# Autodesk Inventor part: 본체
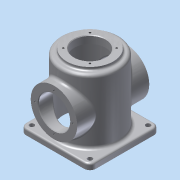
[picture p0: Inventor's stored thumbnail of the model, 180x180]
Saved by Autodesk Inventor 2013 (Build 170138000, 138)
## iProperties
Created: 2015-10
Part Number: 본체
Material: 알루미늄 6061
Document SubType Name: Modeling
Designer: Administrator
Density: 2.71 g/cm^3
Mass: 985.996 g
Surface Area: 1037.34 cm^2
Volume: 363.836 cm^3
Author: Administrator
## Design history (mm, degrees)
sketch "스케치1"
  geometry: L1 (-50, 60)-(50, 60); L2 (60, 50)-(60, -50); L3 (50, -60)-(-50, -60); L4 (-60, -50)-(-60, 50); A1 r 10 centre (-50, 50) between (-50, 60) and (-60, 50); A2 r 10 centre (-50, -50) between (-60, -50) and (-50, -60); A3 r 10 centre (50, -50) between (50, -60) and (60, -50); A4 r 10 centre (50, 50) between (60, 50) and (50, 60); 5 further points
  constraints: 8 end point, 8 point on circle, 8 tangent, 4 centre point, 4 point on line, 3 equal radius, 2 midpoint, 2 parallel, 2 perpendicular, 1 horizontal, 1 horizontal alignment, 1 vertical alignment
  dimensions: "d0" = 120 distance of point (-60, 60) point (60, 60); "d2" = 10 radius of A1
extrude "돌출1" new body sketch "스케치1" distance "d3" = 10; taper "d4" = 0 deg
sketch "스케치2"
  geometry: C1 r 50 at (0, 0); 1 further point
  constraints: 1 centre point, 1 coincident
  dimensions: "d5" = 100 diameter of C1
extrude "돌출2" join sketch "스케치2" distance "d7" = 110; taper "d8" = 0 deg
sketch "스케치3"
  geometry: C1 r 40 at (0, 0); 1 further point
  constraints: 1 centre point, 1 coincident
  dimensions: "d9" = 80 diameter of C1
extrude "돌출3" join sketch "스케치3" distance "d11" = 5; taper "d12" = 0 deg
sketch "스케치4"
  geometry: C1 r 40 at (0, 60); 1 further point
  constraints: 1 centre point, 1 vertical alignment
  dimensions: "d13" = 80 diameter of C1; "d15" = 60 distance of point (0, 0) C1.centre
extrude "돌출4" join sketch "스케치4" stored distance "d16" = 124; taper "d17" = 0 deg
node "작업 평면1"
sketch "스케치5"
  geometry: L1 (-39.988, 60.696)-(-39.988, 79.304); L2 (-39.988, 79.304)-(39.988, 79.304); L3 (39.988, 79.304)-(39.988, 60.696); L4 (39.988, 60.696)-(-39.988, 60.696); 4 further points
  constraints: 2 midpoint, 2 vertical alignment, 1 horizontal alignment, 2 other
  dimensions: "d19" = 70 distance of point (0, 0) point (0, 70)
feature "엠보싱1" sketch "스케치5" dims "d0" = 120, "d2" = 10, "d9" = 80, "d20" = 0.5, "d21" = 0
hole "구멍1" diameter "d24" = 54; stored, may be unused: countersink angle "d28" = 90 deg, drill point angle "d30" = 0 deg; dims "d22" = 10, "d23" = 10, "d25" = 6, "d26" = 90, "d27" = 112, "d29" = 125
hole "구멍2" diameter "d33" = 54; stored, may be unused: countersink angle "d37" = 90 deg, drill point angle "d39" = 0 deg; dims "d31" = 10, "d32" = 10, "d34" = 6, "d35" = 90, "d36" = 112, "d38" = 125
sketch "스케치6"
  geometry: A1 r 32.5 centre (0, 0) between (0, 32.5) and (0, -32.5); 3 further points
  constraints: 4 point on circle, 3 vertical alignment, 2 horizontal alignment, 1 centre point
  dimensions: "d40" = 60 distance of point (0, -60) A1.centre; "d41" = 65 diameter of A1
hole "구멍3" sketch "스케치6" at (0, 32.5), (0, -32.5), (-32.5, 0), (32.5, 0) diameter "d42" = 3.242; stored, may be unused: countersink angle "d46" = 90 deg, drill point angle "d48" = 118 deg; dims "d43" = 8, "d44" = 90, "d45" = 112, "d47" = 10
sketch "스케치7"
  geometry: A1 r 32.5 centre (0, 0) between (-22.981, 22.981) and (22.981, 22.981); 3 further points
  constraints: 4 point on circle, 2 horizontal alignment, 2 vertical alignment, 1 centre point, 1 coincident
  dimensions: "d49" = 65 diameter of A1; "d51" = 90 deg dimension on point (0, 0) A1.end A1.start
hole "구멍4" sketch "스케치7" at (-22.981, 22.981), (22.981, 22.981), (-22.981, -22.981), (22.981, -22.981) diameter "d53" = 3.242; stored, may be unused: countersink angle "d57" = 90 deg, drill point angle "d59" = 118 deg; dims "d54" = 8, "d55" = 90, "d56" = 112, "d58" = 10
sketch "스케치8"
  geometry: C1 r 4 at (-50, 50); C2 r 4 at (50, 50); C3 r 4 at (50, -50); C4 r 4 at (-50, -50); 1 further point
  constraints: 4 centre point, 3 equal radius, 2 horizontal alignment, 2 vertical alignment
  dimensions: "d60" = 100 distance of C2.centre C1.centre; "d62" = 50 horizontal distance of point (0, 0) C1.centre; "d63" = 100 distance of C4.centre C1.centre; "d64" = 50 horizontal distance of point (0, 0) C1.centre; "d65" = 8 diameter of C1
extrude "돌출5" cut sketch "스케치8" distance "d66" = 124; taper "d67" = 0 deg
chamfer "모따기1" distance "d68" = 1; stored, may be unused: second distance "d69" = 2, angle "d70" = 45 deg
chamfer "모따기2" distance "d71" = 3; stored, may be unused: second distance "d72" = 2, angle "d73" = 45 deg
fillet "모깎기1" dims "d74" = 5
fillet "모깎기2" dims "d75" = 5
fillet "모깎기3" dims "d76" = 5
fillet "모깎기4" dims "d77" = 3
fillet "모깎기5" dims "d78" = 3
node "솔리드1"
mirror "대칭1"
other parameters: "d18" = -13.25
